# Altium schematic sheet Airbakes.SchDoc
size A4
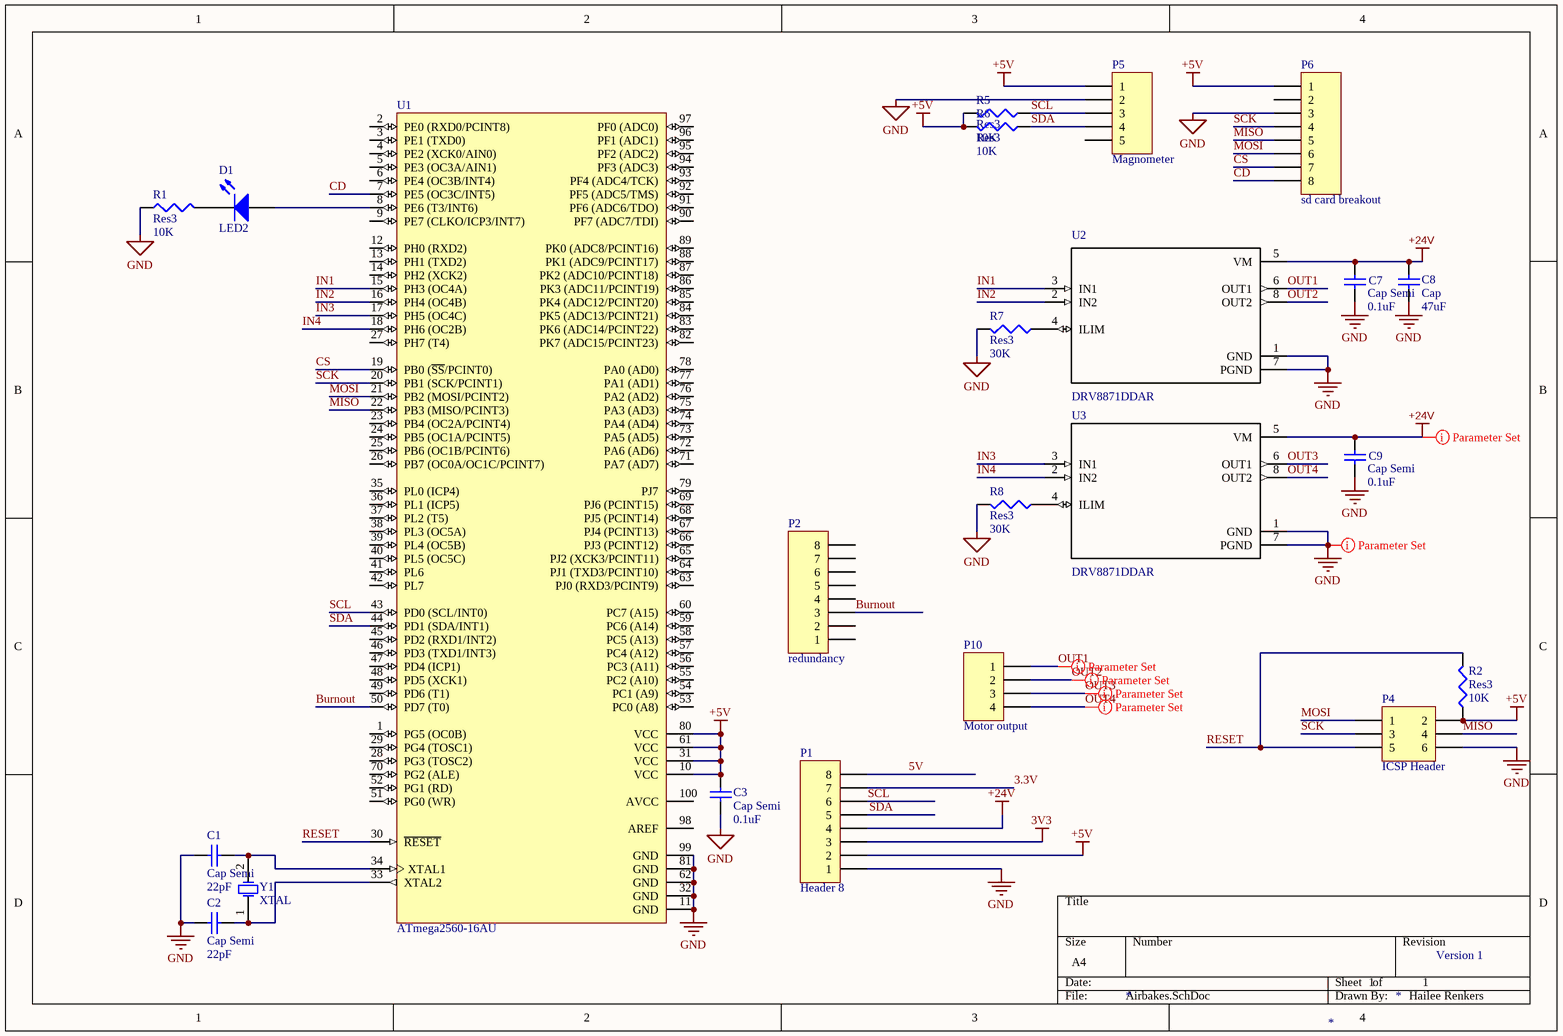
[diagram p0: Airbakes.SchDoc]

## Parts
C1  Cap Semi  value 22pF  [C1206]
C2  Cap Semi  value 22pF  [C1206]
C3  Cap Semi  value 0.1uF  [C1206]
C7  Cap Semi  value 0.1uF  [C1206]
C8  Cap  value 47uF  [RAD-0.3]
C9  Cap Semi  value 0.1uF  [C1206]
D1  LED2  [3.2X1.6X1.1]
P1  Header 8  [HDR1X8]
P2  redundancy  [HDR1X8]
P4  ICSP Header  [HDR2X3]
P5  Magnometer  [HDR1X5]
P6  sd card breakout  [HDR1X8]
P10  Motor output  [HDR1X4]
R1  Res3  value 10K  [J1-0603]
R2  Res3  value 10K  [J1-0603]
R5  Res3  value 10K  [J1-0603]
R6  Res3  value 10K  [J1-0603]
R7  Res3  value 30K  [J1-0603]
R8  Res3  value 30K  [J1-0603]
U1  ATmega2560-16AU  [100A_N]
U2  DRV8871DDAR  [SOIC127P600X170-8N]
U3  DRV8871DDAR  [SOIC127P600X170-8N]
Y1  XTAL  [R38]

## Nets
3V3: P1.3
+5V: C3.2 P1.2 P4.2 P5.1 P6.1 R2.1 R5.2 R6.2 U1.10(VCC) U1.31(VCC) U1.61(VCC) U1.80(VCC)
+24V: C7.2 C8.1 C9.2 P1.4 U2.5(VM) U3.5(VM)
GND: C1.1 C2.1 C3.1 C7.1 C8.2 C9.1 P1.1 P4.6 P5.2 P6.3 R1.2 R7.2 R8.2 U1.11(GND) U1.32(GND) U1.62(GND) U1.81(GND) U1.99(GND) U2.1(GND) U2.7(PGND) U3.1(GND) U3.7(PGND)
3.3V: P1.7
5V: P1.8
Burnout: P2.3 U1.50(PD7_(T0))
CD: P6.8 U1.7(PE5_(OC3C/INT5))
CS: P6.7 U1.19(PB0_(~{SS}/PCINT0))
IN1: U1.15(PH3_(OC4A)) U2.3(IN1)
IN2: U1.16(PH4_(OC4B)) U2.2(IN2)
IN3: U1.17(PH5_(OC4C)) U3.3(IN1)
IN4: U1.18(PH6_(OC2B)) U3.2(IN2)
MISO: P4.4 P6.5 U1.22(PB3_(MISO/PCINT3))
MOSI: P4.1 P6.6 U1.21(PB2_(MOSI/PCINT2))
OUT1: P10.1 U2.6(OUT1)
OUT2: P10.2 U2.8(OUT2)
OUT3: P10.3 U3.6(OUT1)
OUT4: P10.4 U3.8(OUT2)
RESET: P4.5 R2.2 U1.30(~{RESET})
SCK: P4.3 P6.4 U1.20(PB1_(SCK/PCINT1))
SCL: P1.6 P5.3 R5.1 U1.43(PD0_(SCL/INT0))
SDA: P1.5 P5.4 R6.1 U1.44(PD1_(SDA/INT1))
NetC1_2: C1.2 U1.34(XTAL1) Y1.2(OSC2)
NetC2_2: C2.2 U1.33(XTAL2) Y1.1(OSC1)
NetD1_1: D1.1(A) U1.8(PE6_(T3/INT6))
NetD1_2: D1.2(K) R1.1
NetR7_1: R7.1 U2.4(ILIM)
NetR8_1: R8.1 U3.4(ILIM)

Not connected (* = marked no-connect by the designer): P2 1 2 4 5 6 7 8; P5 5; P6 2; U1 1(PG5_(OC0B)) 2(PE0_(RXD0/PCINT8)) 3(PE1_(TXD0)) 4(PE2_(XCK0/AIN0)) 5(PE3_(OC3A/AIN1)) 6(PE4_(OC3B/INT4)) 9(PE7_(CLKO/ICP3/INT7)) 12(PH0_(RXD2)) 13(PH1_(TXD2)) 14(PH2_(XCK2)) 23(PB4_(OC2A/PCINT4)) 24(PB5_(OC1A/PCINT5)) 25(PB6_(OC1B/PCINT6)) 26(PB7_(OC0A/OC1C/PCINT7)) 27(PH7_(T4)) 28(PG3_(TOSC2)) 29(PG4_(TOSC1)) 35(PL0_(ICP4)) 36(PL1_(ICP5)) 37(PL2_(T5)) 38(PL3_(OC5A)) 39(PL4_(OC5B)) 40(PL5_(OC5C)) 41(PL6) 42(PL7) 45(PD2_(RXD1/INT2)) 46(PD3_(TXD1/INT3)) 47(PD4_(ICP1)) 48(PD5_(XCK1)) 49(PD6_(T1)) 51(PG0_(WR)) 52(PG1_(RD)) 53(PC0_(A8)) 54(PC1_(A9)) 55(PC2_(A10)) 56(PC3_(A11)) 57(PC4_(A12)) 58(PC5_(A13)) 59(PC6_(A14)) 60(PC7_(A15)) 63(PJ0_(RXD3/PCINT9)) 64(PJ1_(TXD3/PCINT10)) 65(PJ2_(XCK3/PCINT11)) 66(PJ3_(PCINT12)) 67(PJ4_(PCINT13)) 68(PJ5_(PCINT14)) 69(PJ6_(PCINT15)) 70(PG2_(ALE)) 71(PA7_(AD7)) 72(PA6_(AD6)) 73(PA5_(AD5)) 74(PA4_(AD4)) 75(PA3_(AD3)) 76(PA2_(AD2)) 77(PA1_(AD1)) 78(PA0_(AD0)) 79(PJ7) 82(PK7_(ADC15/PCINT23)) 83(PK6_(ADC14/PCINT22)) 84(PK5_(ADC13/PCINT21)) 85(PK4_(ADC12/PCINT20)) 86(PK3_(ADC11/PCINT19)) 87(PK2_(ADC10/PCINT18)) 88(PK1_(ADC9/PCINT17)) 89(PK0_(ADC8/PCINT16)) 90(PF7_(ADC7/TDI)) 91(PF6_(ADC6/TDO)) 92(PF5_(ADC5/TMS)) 93(PF4_(ADC4/TCK)) 94(PF3_(ADC3)) 95(PF2_(ADC2)) 96(PF1_(ADC1)) 97(PF0_(ADC0)) 98(AREF) 100(AVCC)

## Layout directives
rule Width Constraint [Pref Width = 0.5mm    Min Width = 0.254mm    Max Width = 0.5mm]: +24V, OUT1, OUT2, OUT3, OUT4
rule Width Constraint [Pref Width = 0.3mm    Min Width = 0.254mm    Max Width = 0.3mm]: GND

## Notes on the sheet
- 1
- Version 1
- Hailee Renkers

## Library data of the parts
C1-C3 C7 C9 = Cap Semi: Capacitor (Semiconductor SIM Model)
C8 = Cap: Capacitor
D1 = LED2: Typical RED, GREEN, YELLOW, AMBER GaAs LED
P1 P2 P6 = Header 8: Header, 8-Pin
P4 = Header 3X2: Header, 3-Pin, Dual row
P5 = Header 5: Header, 5-Pin
P10 = Header 4: Header, 4-Pin
R1 R2 R5-R8 = Res3: Resistor
U1 = ATmega2560-16AU: 8-bit AVR Microcontroller, 4.5-5.5V, 256KB Flash, 4KB EEPROM, 8KB SRAM, 86 GPIO pins, 100-pin TQFP, Industrial Grade (-40°C to 85°C), Pb-Free
U2 U3 = DRV8871DDAR: 3.6A Brushed DC Motor Driver with Integrated Current Sensing (PWM Ctrl) 8-SO PowerPAD -40 to 125; MF: Texas Instruments
Y1 = XTAL: Crystal Oscillator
